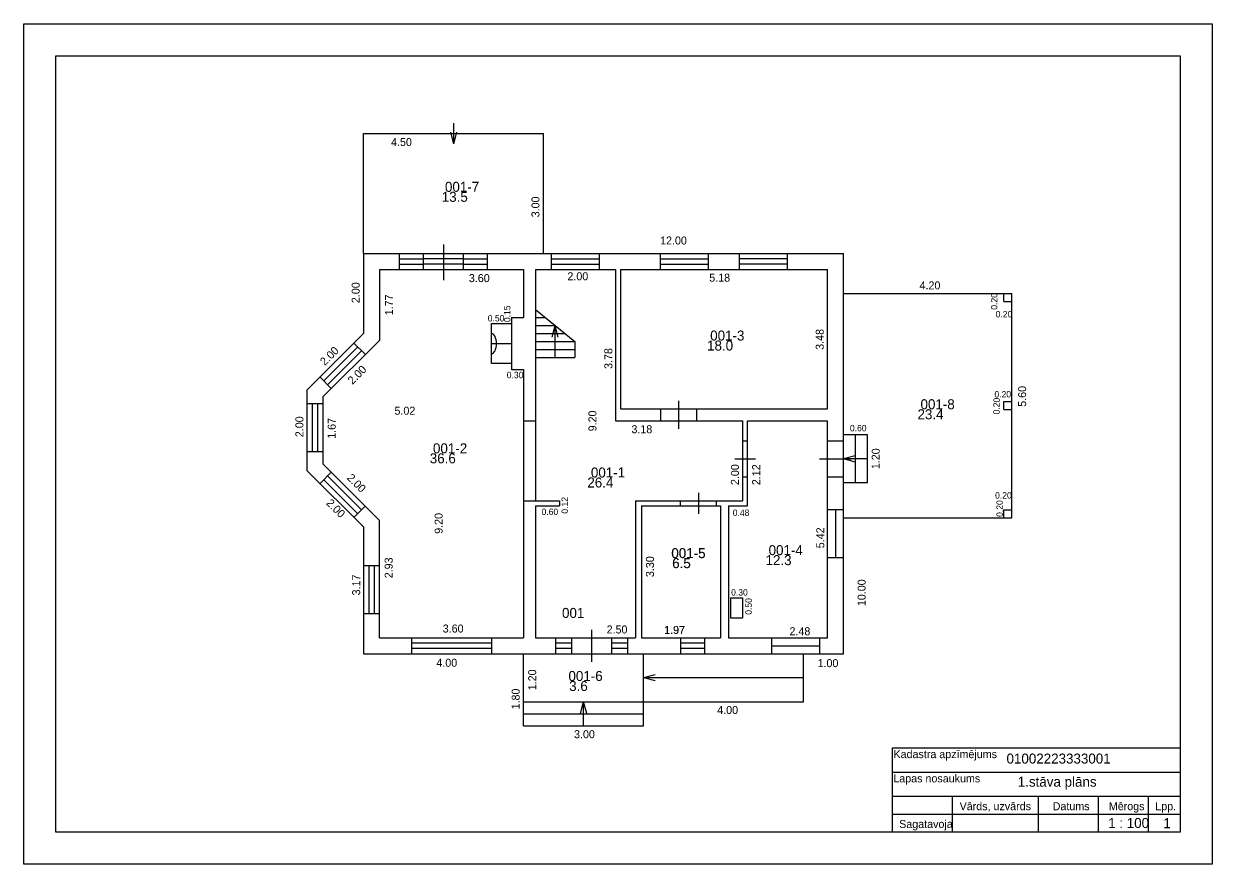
# Model space of a CAD drawing. Extents: x 509118.3 to 509148, y 311125.9 to 311169.7.
# Drawn here: x 509118.26 to 509147.96, y 311148.67 to 311169.67 of the extents above; entities that cross this region are included whole.
import ezdxf

# ---------------------------------------------------------------- set-up
doc = ezdxf.new("R2010")
doc.units = 0
for name, color, linetype in [('BUVE_EKAS_RKTL_FORM_#', 7, 'Continuous'), ('BUVE_EKAS_STPL_ASIE_#', 7, 'Continuous'), ('BUVE_EKAS_STPL_PLOG_#', 7, 'Continuous'), ('BUVE_EKAS_STPL_RAM#_#', 7, 'Continuous'), ('BUVE_EKAS_STPL_SIEN_#', 7, 'Continuous'), ('BUVE_TELP_STPL_ELEM_#', 7, 'Continuous'), ('BUVE_TELP_STPL_IZMR_#', 7, 'Continuous'), ('BUVE_TELP_STPL_KADR_#', 7, 'Continuous'), ('BUVE_TELP_STPL_PLAT_#', 7, 'Continuous'), ('BUVE_TELP_STPL_TLNR_#', 7, 'Continuous')]:
    doc.layers.add(name, color=color, linetype=linetype)

# ---------------------------------------------------------------- blocks, each defined once
blk = doc.blocks.new('kamins')
at = {"layer": 'BUVE_TELP_STPL_ELEM_#'}
for p, q in [((-0.5, -1), (-0.5, 0)), ((-0.5, 0), (0.5, 0)), ((0, -1), (0, 0)), ((0.5, 0), (0.5, -1)), ((0.5, -1), (-0.5, -1))]:
    blk.add_line(p, q, dxfattribs=at)
blk.add_arc((0, -1), 0.25, 0, 180, dxfattribs=at)
blk = doc.blocks.new('bulta')
at = {"layer": 'BUVE_TELP_STPL_ELEM_#'}
for p in [(-0.29, 0.078), (-0.29, -0.078)]:
    blk.add_line(p, (0, 0), dxfattribs=at)
blk = doc.blocks.new('edurvis')
at = {"layer": 'BUVE_TELP_STPL_ELEM_#'}
for p, q in [((0.5, -0.5), (0.5, 1.5)), ((0, 0), (0, 1)), ((1, 0), (1, 1))]:
    blk.add_line(p, q, dxfattribs=at)
blk = doc.blocks.new('elogs')
at = {"layer": 'BUVE_TELP_STPL_ELEM_#'}
for p, q in [((0, 0), (0, 1)), ((1, 0), (1, 1)), ((1, 0.67), (0, 0.67)), ((1, 0.33), (0, 0.33))]:
    blk.add_line(p, q, dxfattribs=at)
blk = doc.blocks.new('edurvis_1')
at = {"layer": 'BUVE_TELP_STPL_ELEM_#'}
for p, q in [((0.5, -1.667), (0.5, 2.667)), ((0, 0), (0, 1)), ((1, 0), (1, 1))]:
    blk.add_line(p, q, dxfattribs=at)
blk = doc.blocks.new('edurvis_2')
at = {"layer": 'BUVE_TELP_STPL_ELEM_#'}
for p, q in [((0.5, 2.667), (0.5, -1.667)), ((0, 0), (0, 1)), ((1, 0), (1, 1))]:
    blk.add_line(p, q, dxfattribs=at)
blk = doc.blocks.new('edurvis_3')
at = {"layer": 'BUVE_TELP_STPL_ELEM_#'}
for p, q in [((0.5, -0.667), (0.5, 1.667)), ((0, 0), (0, 1)), ((1, 0), (1, 1))]:
    blk.add_line(p, q, dxfattribs=at)
blk = doc.blocks.new('elogs_stdu')
at = {"layer": 'BUVE_TELP_STPL_ELEM_#'}
for p, q in [((0.5, 1.576), (0.5, -0.67)), ((0, 0), (0, 1)), ((1, 0), (1, 1)), ((1, 0.67), (0, 0.67)), ((1, 0.33), (0, 0.33))]:
    blk.add_line(p, q, dxfattribs=at)
blk = doc.blocks.new('d_aile')
at = {"layer": 'BUVE_TELP_STPL_ELEM_#'}
for p, q in [((0, 0), (0, 1)), ((1, 0), (1, 1))]:
    blk.add_line(p, q, dxfattribs=at)
blk = doc.blocks.new('ramis')
at = {"layer": 'BUVE_EKAS_RKTL_FORM_#'}
blk.add_lwpolyline([(0, 0), (-1, 0), (-1, 1), (0, 1)], close=True, dxfattribs=at)

msp = doc.modelspace()

# ---------------------------------------------------------------- linework, layer by layer
at = {"layer": 'BUVE_EKAS_RKTL_FORM_#'}
for p, q in [((509139.959, 311151.571), (509139.959, 311149.471)), ((509147.159, 311151.571), (509139.959, 311151.571)), ((509147.159, 311151.571), (509147.159, 311149.471)), ((509139.959, 311150.971), (509139.959, 311149.471)), ((509139.959, 311150.971), (509147.159, 311150.971)), ((509139.959, 311150.371), (509147.159, 311150.371)), ((509141.459, 311150.371), (509141.459, 311149.471)), ((509143.609, 311150.371), (509143.609, 311149.471)), ((509145.109, 311150.371), (509145.109, 311149.471)), ((509146.359, 311150.371), (509146.359, 311149.471)), ((509139.959, 311149.921), (509147.159, 311149.921)), ((509147.159, 311149.471), (509139.959, 311149.471))]:
    msp.add_line(p, q, dxfattribs=at)
msp.add_lwpolyline([(509119.059, 311168.871), (509147.159, 311168.871), (509147.159, 311149.471), (509119.059, 311149.471)], close=True, dxfattribs=at)
at = {"layer": 'BUVE_EKAS_STPL_ASIE_#'}
for p, q in [((509126.748, 311163.929), (509126.748, 311161.929)), ((509126.748, 311163.929), (509138.748, 311163.929)), ((509138.748, 311153.929), (509138.748, 311163.929)), ((509138.748, 311162.929), (509142.948, 311162.929)), ((509142.748, 311162.729), (509142.748, 311162.929)), ((509142.948, 311157.329), (509142.948, 311162.929)), ((509142.748, 311162.729), (509142.948, 311162.729)), ((509125.332, 311160.513), (509126.748, 311161.929)), ((509125.332, 311160.513), (509125.332, 311158.513)), ((509142.748, 311160.029), (509142.748, 311160.229)), ((509142.748, 311160.229), (509142.948, 311160.229)), ((509142.748, 311160.029), (509142.948, 311160.029)), ((509125.332, 311158.513), (509126.748, 311157.098)), ((509142.748, 311157.329), (509142.748, 311157.529)), ((509142.748, 311157.529), (509142.948, 311157.529)), ((509138.748, 311157.329), (509142.948, 311157.329)), ((509126.748, 311157.098), (509126.748, 311153.929)), ((509126.748, 311153.929), (509138.748, 311153.929))]:
    msp.add_line(p, q, dxfattribs=at)
at = {"layer": 'BUVE_EKAS_STPL_PLOG_#'}
for p, q in [((509138.748, 311157.529), (509138.348, 311157.529)), ((509138.548, 311157.529), (509138.548, 311156.329)), ((509138.748, 311156.329), (509138.348, 311156.329)), ((509136.948, 311154.329), (509136.948, 311153.929)), ((509136.948, 311154.129), (509138.148, 311154.129)), ((509138.148, 311154.329), (509138.148, 311153.929))]:
    msp.add_line(p, q, dxfattribs=at)
at = {"layer": 'BUVE_EKAS_STPL_SIEN_#'}
for p, q in [((509127.148, 311163.529), (509130.748, 311163.529)), ((509127.148, 311163.529), (509127.148, 311161.759)), ((509127.148, 311163.529), (509130.748, 311163.529)), ((509130.748, 311163.529), (509130.748, 311162.329)), ((509131.048, 311163.529), (509131.048, 311157.749)), ((509131.048, 311163.529), (509133.048, 311163.529)), ((509133.048, 311163.529), (509133.048, 311159.749)), ((509133.168, 311163.529), (509138.348, 311163.529)), ((509133.168, 311163.529), (509133.168, 311160.049)), ((509138.348, 311160.049), (509138.348, 311163.529)), ((509130.448, 311162.329), (509130.448, 311162.179)), ((509130.448, 311162.329), (509130.748, 311162.329)), ((509127.148, 311161.759), (509125.732, 311160.348)), ((509130.448, 311161.179), (509130.448, 311161.029)), ((509130.448, 311161.029), (509130.748, 311161.029)), ((509130.748, 311161.029), (509130.748, 311154.329)), ((509125.732, 311160.348), (509125.732, 311158.678)), ((509133.168, 311160.049), (509138.348, 311160.049)), ((509133.048, 311159.749), (509136.228, 311159.749)), ((509136.228, 311157.749), (509136.228, 311159.749)), ((509136.348, 311157.629), (509136.348, 311159.749)), ((509136.348, 311159.749), (509138.348, 311159.749)), ((509138.348, 311154.329), (509138.348, 311159.749)), ((509125.732, 311158.678), (509127.148, 311157.259)), ((509131.048, 311157.749), (509131.648, 311157.749)), ((509131.648, 311157.749), (509131.648, 311157.629)), ((509133.548, 311157.749), (509136.228, 311157.749)), ((509133.548, 311157.749), (509133.548, 311154.329)), ((509131.048, 311157.629), (509131.048, 311154.329)), ((509131.048, 311157.629), (509131.648, 311157.629)), ((509133.698, 311157.629), (509135.668, 311157.629)), ((509133.698, 311157.629), (509133.698, 311154.329)), ((509133.698, 311157.629), (509135.668, 311157.629)), ((509133.698, 311157.629), (509133.698, 311154.329)), ((509135.668, 311157.629), (509135.668, 311154.329)), ((509135.668, 311157.629), (509135.668, 311154.329)), ((509135.868, 311157.629), (509136.348, 311157.629)), ((509135.868, 311157.629), (509135.868, 311154.329)), ((509127.148, 311154.329), (509127.148, 311157.259)), ((509135.918, 311155.329), (509135.918, 311154.829)), ((509135.918, 311155.329), (509136.218, 311155.329)), ((509136.218, 311155.329), (509136.218, 311154.829)), ((509135.918, 311154.829), (509136.218, 311154.829)), ((509127.148, 311154.329), (509130.748, 311154.329)), ((509131.048, 311154.329), (509133.548, 311154.329)), ((509133.698, 311154.329), (509135.668, 311154.329)), ((509133.698, 311154.329), (509135.668, 311154.329)), ((509135.868, 311154.329), (509138.348, 311154.329))]:
    msp.add_line(p, q, dxfattribs=at)
at = {"layer": 'BUVE_TELP_STPL_ELEM_#'}
for p, q in [((509126.748, 311166.929), (509131.248, 311166.929)), ((509126.748, 311163.929), (509126.748, 311166.929)), ((509126.748, 311163.929), (509126.748, 311166.929)), ((509131.248, 311163.929), (509131.248, 311166.929)), ((509131.248, 311163.929), (509131.248, 311166.929)), ((509131.048, 311162.529), (509132.028, 311161.729)), ((509131.048, 311162.329), (509131.293, 311162.329)), ((509131.048, 311162.129), (509131.538, 311162.129)), ((509131.048, 311161.929), (509131.783, 311161.929)), ((509126.605, 311161.597), (509125.756, 311160.749)), ((509126.795, 311161.407), (509126.511, 311161.692)), ((509131.048, 311161.729), (509132.028, 311161.729)), ((509132.028, 311161.729), (509132.028, 311161.329)), ((509126.701, 311161.5), (509125.852, 311160.653)), ((509131.048, 311161.529), (509132.028, 311161.529)), ((509131.048, 311161.329), (509132.028, 311161.329)), ((509125.945, 311160.559), (509125.662, 311160.843)), ((509139.348, 311159.399), (509138.748, 311159.399)), ((509139.048, 311158.199), (509139.048, 311159.399)), ((509139.348, 311158.199), (509139.348, 311159.399)), ((509125.944, 311158.465), (509125.662, 311158.184)), ((509126.699, 311157.523), (509125.852, 311158.373)), ((509126.604, 311157.428), (509125.756, 311158.277)), ((509139.348, 311158.199), (509138.748, 311158.199)), ((509126.792, 311157.616), (509126.511, 311157.335)), ((509130.748, 311152.129), (509130.748, 311153.929)), ((509133.748, 311152.129), (509133.748, 311153.929)), ((509137.748, 311152.729), (509137.748, 311153.929)), ((509130.748, 311152.729), (509133.748, 311152.729)), ((509133.748, 311152.729), (509137.748, 311152.729)), ((509130.748, 311152.429), (509133.748, 311152.429)), ((509130.748, 311152.129), (509133.748, 311152.129))]:
    msp.add_line(p, q, dxfattribs=at)
for points in [[(509128.998, 311167.187), (509128.998, 311166.671)], [(509131.538, 311161.329), (509131.538, 311162.129)], [(509139.348, 311158.799), (509138.748, 311158.799)], [(509137.748, 311153.329), (509133.748, 311153.329)], [(509132.248, 311152.129), (509132.248, 311152.729)]]:
    msp.add_lwpolyline(points, dxfattribs=at)

# ---------------------------------------------------------------- block references
at = {"layer": 'BUVE_EKAS_RKTL_FORM_#', "xscale": 29.6999999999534, "yscale": 20.9999999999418}
msp.add_blockref('ramis', (509147.959, 311148.671), dxfattribs=at)
at = {"layer": 'BUVE_TELP_STPL_ELEM_#'}
for p, rotation in [((509128.998, 311166.671), -90.00000000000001), ((509131.538, 311162.129), 90), ((509138.748, 311158.799), 180), ((509133.748, 311153.329), 180), ((509132.248, 311152.729), 90)]:
    msp.add_blockref('bulta', p, dxfattribs=dict(at, rotation=rotation))
for name, p, yscale in [('elogs_stdu', (509128.248, 311163.529), 0.4), ('edurvis', (509131.948, 311154.329), -0.4)]:
    msp.add_blockref(name, p, dxfattribs=dict(at, yscale=yscale))
for name, p, xscale, yscale, rotation in [('elogs', (509128.248, 311163.529), 0.6, -0.4, 180), ('elogs', (509129.848, 311163.529), 0.6, -0.4, 180), ('elogs', (509132.648, 311163.529), 1.2, -0.4, 180), ('elogs', (509135.368, 311163.529), 1.2, -0.4, 180), ('elogs', (509125.732, 311158.978), 1.2, 0.4, 90), ('edurvis_3', (509135.068, 311160.049), 0.9, 0.3, 180), ('d_aile', (509130.748, 311157.749), 2, -0.3, 89.99999999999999), ('edurvis_1', (509136.228, 311159.249), 0.9, 0.12, -90.00000000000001), ('edurvis', (509138.348, 311159.249), 0.9, 0.4, -90.00000000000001), ('edurvis_2', (509135.568, 311157.629), 0.9, -0.12, 180), ('elogs', (509127.148, 311154.929), 1.2, 0.4, 90)]:
    msp.add_blockref(name, p, dxfattribs=dict(at, xscale=xscale, yscale=yscale, rotation=rotation))
for p, xscale, yscale in [((509136.148, 311163.529), 1.2, 0.4), ((509127.948, 311154.329), 2, -0.4), ((509131.548, 311154.329), 0.4, -0.4000000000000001), ((509132.948, 311154.329), 0.4, -0.4000000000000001), ((509134.668, 311154.329), 0.6, -0.4)]:
    msp.add_blockref('elogs', p, dxfattribs=dict(at, xscale=xscale, yscale=yscale))
at = {"layer": 'BUVE_TELP_STPL_ELEM_#', "yscale": 0.5, "rotation": -90.00000000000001}
msp.add_blockref('kamins', (509130.448, 311161.679), dxfattribs=at)

# ---------------------------------------------------------------- texts
at = {"layer": 'BUVE_EKAS_STPL_RAM#_#'}
for s, height, p in [('Kadastra apzīmējums', 0.2, (509139.994, 311151.322)), ('01002223333001', 0.25, (509142.818, 311151.186)), ('Lapas nosaukums', 0.2, (509139.99, 311150.716)), ('1.stāva plāns', 0.25, (509143.099, 311150.608)), ('Vārds, uzvārds', 0.2, (509141.646, 311150.021)), ('Datums', 0.2, (509143.972, 311150.021)), ('Mērogs', 0.2, (509145.375, 311150.021)), ('Lpp.', 0.2, (509146.536, 311150.021)), ('Sagatavoja', 0.2, (509140.136, 311149.576)), ('1 : 100', 0.25, (509145.358, 311149.576)), ('1', 0.25, (509146.738, 311149.572))]:
    msp.add_text(s, height=height, dxfattribs=at).set_placement(p)
at = {"layer": 'BUVE_TELP_STPL_IZMR_#'}
for s, height, p in [('4.50', 0.2, (509127.438, 311166.616)), ('12.00', 0.2, (509134.161, 311164.156)), ('3.60', 0.2, (509129.382, 311163.216)), ('3.60', 0.2, (509129.383, 311163.216)), ('2.00', 0.2, (509131.845, 311163.262)), ('5.18', 0.2, (509135.39, 311163.227)), ('4.20', 0.2, (509140.645, 311163.034)), ('0.20', 0.16, (509142.546, 311162.334)), ('0.50', 0.16, (509129.854, 311162.233)), ('0.30', 0.16, (509130.329, 311160.815)), ('0.20', 0.16, (509142.516, 311160.334)), ('5.02', 0.2, (509127.523, 311159.903)), ('3.18', 0.2, (509133.445, 311159.44)), ('0.60', 0.16, (509138.904, 311159.487)), ('0.20', 0.16, (509142.533, 311157.807)), ('0.60', 0.16, (509131.198, 311157.396)), ('0.48', 0.16, (509135.976, 311157.373)), ('0.30', 0.16, (509135.936, 311155.383)), ('3.60', 0.2, (509128.729, 311154.46)), ('2.50', 0.2, (509132.825, 311154.437)), ('1.97', 0.2, (509134.26, 311154.424)), ('1.97', 0.2, (509134.265, 311154.424)), ('2.48', 0.2, (509137.395, 311154.392)), ('4.00', 0.2, (509128.57, 311153.605)), ('1.00', 0.2, (509138.096, 311153.595)), ('4.00', 0.2, (509135.589, 311152.425)), ('3.00', 0.2, (509132.011, 311151.82))]:
    msp.add_text(s, height=height, dxfattribs=at).set_placement(p)
for s, height, rotation, p in [('3.00', 0.2, 90, (509131.146, 311164.835)), ('2.00', 0.2, 90, (509126.653, 311162.691)), ('1.77', 0.2, 90, (509127.486, 311162.387)), ('0.20', 0.16, 90, (509142.59, 311162.525)), ('0.15', 0.16, 90, (509130.42, 311162.216)), ('3.48', 0.2, 90, (509138.25, 311161.524)), ('2.00', 0.2, 45, (509125.783, 311161.117)), ('3.78', 0.2, 90, (509132.967, 311161.046)), ('2.00', 0.2, 44.9126, (509126.473, 311160.646)), ('2.00', 0.2, 44.9126, (509126.473, 311160.647)), ('5.60', 0.2, 90, (509143.309, 311160.101)), ('0.20', 0.16, 90, (509142.649, 311159.91)), ('2.00', 0.2, 90, (509125.247, 311159.342)), ('1.67', 0.2, 90, (509126.054, 311159.301)), ('9.20', 0.2, 90, (509132.57, 311159.487)), ('1.20', 0.2, 90, (509139.649, 311158.542)), ('2.00', 0.2, 90, (509136.13, 311158.145)), ('2.12', 0.2, 90, (509136.662, 311158.143)), ('2.00', 0.2, 314.9382, (509126.32, 311158.31)), ('2.00', 0.2, 315, (509125.802, 311157.679)), ('0.12', 0.16, 90, (509131.858, 311157.431)), ('0.20', 0.16, 90, (509142.726, 311157.35)), ('9.20', 0.2, 90, (509128.727, 311156.927)), ('5.42', 0.2, 90, (509138.264, 311156.566)), ('2.93', 0.2, 90, (509127.478, 311155.816)), ('3.30', 0.2, 90, (509134.007, 311155.846)), ('3.30', 0.2, 90, (509134.007, 311155.845)), ('3.17', 0.2, 90, (509126.666, 311155.388)), ('10.00', 0.2, 90, (509139.297, 311155.12)), ('0.50', 0.16, 90, (509136.452, 311154.904)), ('1.20', 0.2, 90, (509131.065, 311153.018)), ('1.80', 0.2, 90, (509130.652, 311152.539))]:
    msp.add_text(s, height=height, rotation=rotation, dxfattribs=at).set_placement(p)
at = {"layer": 'BUVE_TELP_STPL_KADR_#'}
msp.add_text('001', height=0.25, dxfattribs=at).set_placement((509131.71, 311154.825))
at = {"layer": 'BUVE_TELP_STPL_PLAT_#'}
for s, p in [('13.5', (509128.705, 311165.222)), ('18.0', (509135.335, 311161.506)), ('23.4', (509140.594, 311159.789)), ('36.6', (509128.405, 311158.688)), ('26.4', (509132.343, 311158.084)), ('6.5', (509134.462, 311156.069)), ('6.5', (509134.465, 311156.069)), ('12.3', (509136.796, 311156.144)), ('3.6', (509131.889, 311152.999))]:
    msp.add_text(s, height=0.25, dxfattribs=at).set_placement(p)
at = {"layer": 'BUVE_TELP_STPL_TLNR_#'}
for s, p in [('001-7', (509128.785, 311165.472)), ('001-3', (509135.413, 311161.756)), ('001-8', (509140.669, 311160.039)), ('001-2', (509128.485, 311158.938)), ('001-1', (509132.432, 311158.334)), ('001-5', (509134.44, 311156.319)), ('001-5', (509134.444, 311156.319)), ('001-4', (509136.873, 311156.394)), ('001-6', (509131.871, 311153.249))]:
    msp.add_text(s, height=0.25, dxfattribs=at).set_placement(p)

doc.saveas('drawing.dxf')
